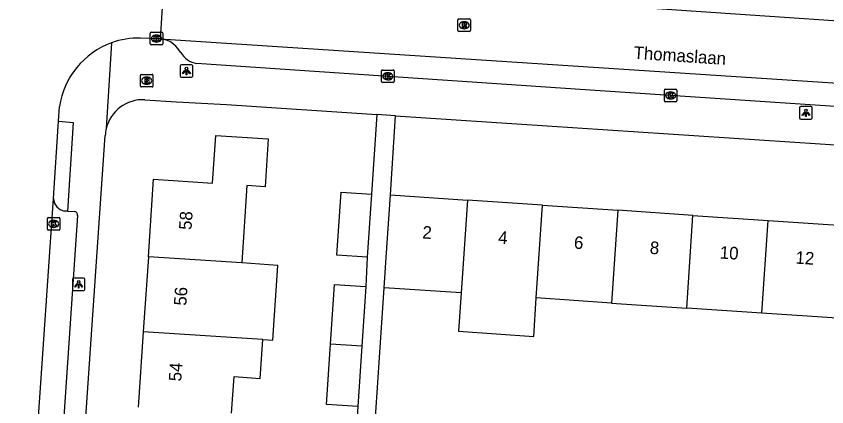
# Model space of a CAD drawing. Extents: x 161848 to 162726, y 385382 to 386521.
# Drawn here: x 162036.6 to 162101.1, y 385964.2 to 385995.3 of the extents above; entities that cross this region are included whole.
import ezdxf

# ---------------------------------------------------------------- set-up
doc = ezdxf.new("R2010")
doc.units = 0
for name, color, linetype in [('IMGEO_Brandkraan', 7, 'Continuous'), ('IMGEO_Kolk', 7, 'Continuous'), ('IMGEO_Lichtpunt', 7, 'Continuous'), ('IMGEO_Muur', 7, 'Continuous'), ('IMGEO_Openbare_ruimte_label', 7, 'Continuous'), ('IMGEO_Pand', 7, 'Continuous'), ('IMGEO_Pand_nummerreeks', 7, 'Continuous'), ('IMGEO_Rijbaan_lokaal_open', 7, 'Continuous'), ('IMGEO_Rioolput', 7, 'Continuous'), ('IMGEO_Voetpad_open', 7, 'Continuous')]:
    doc.layers.add(name, color=color, linetype=linetype)

msp = doc.modelspace()

# ---------------------------------------------------------------- linework, layer by layer
at = {"layer": 'IMGEO_Brandkraan'}
for p, q in [((162046.491, 385989.738), (162046.491, 385990.59)), ((162046.566, 385990.664), (162047.418, 385990.664)), ((162047.492, 385990.59), (162047.492, 385989.738)), ((162047.002, 385989.884), (162046.977, 385989.884)), ((162046.979, 385990.444), (162047.004, 385990.444)), ((162047.418, 385989.664), (162046.566, 385989.664))]:
    msp.add_line(p, q, dxfattribs=at)
for points in [[(162046.491, 385989.738), (162046.491, 385990.59)], [(162046.566, 385990.664), (162047.418, 385990.664)], [(162047.492, 385990.59), (162047.492, 385989.738)], [(162046.839, 385990.364), (162046.839, 385989.964), (162047.052, 385989.964)], [(162047.07, 385990.364), (162046.839, 385990.364)], [(162047.018, 385990.283), (162046.964, 385990.283), (162046.964, 385990.207)], [(162046.964, 385990.207), (162047.017, 385990.207)], [(162047.026, 385990.131), (162046.964, 385990.131), (162046.964, 385990.05)], [(162046.964, 385990.05), (162047.026, 385990.05)], [(162047.418, 385989.664), (162046.566, 385989.664)]]:
    msp.add_lwpolyline(points, dxfattribs=at)
for centre, radius, start, end in [((162046.568, 385990.588), 0.0765, 91.55205, 178.44795), ((162046.568, 385990.588), 0.0765, 91.55205, 178.44795), ((162047.416, 385990.588), 0.0765, 1.55205, 88.44795), ((162047.416, 385990.588), 0.0765, 1.55205, 88.44795), ((162047.019, 385990.245), 0.0379, 267.82845, 90.93552), ((162047.027, 385990.09), 0.0404, 269.87594, 90.50774), ((162047.058, 385990.215), 0.251, 268.66757, 293.53466), ((162047.074, 385990.219), 0.145, 59.4692, 91.53667), ((162047.099, 385990.266), 0.0922, 285.51372, 58.15012), ((162047.104, 385990.074), 0.105, 301.31148, 78.98903), ((162046.568, 385989.74), 0.0765, 181.55205, 268.44795), ((162046.568, 385989.74), 0.0765, 181.55205, 268.44795), ((162047.416, 385989.74), 0.0765, 271.55205, 358.44795), ((162047.416, 385989.74), 0.0765, 271.55205, 358.44795)]:
    msp.add_arc(centre, radius, start, end, dxfattribs=at)
for centre, major_axis, ratio, start_param, end_param in [((162046.978, 385990.164), (-0.387, 0.002), 0.722429, 4.712389, 7.853982), ((162047.003, 385990.164), (-0.39, 0.002), 0.717154, 1.570796, 4.712389)]:
    msp.add_ellipse(centre, major_axis=major_axis, ratio=ratio, start_param=start_param, end_param=end_param, dxfattribs=at)
at = {"layer": 'IMGEO_Kolk'}
for p, q in [((162047.27, 385993.092), (162047.27, 385993.944)), ((162047.345, 385994.018), (162048.197, 385994.018)), ((162047.758, 385993.798), (162047.783, 385993.798)), ((162048.271, 385993.944), (162048.271, 385993.092)), ((162047.781, 385993.238), (162047.756, 385993.238)), ((162048.197, 385993.018), (162047.345, 385993.018)), ((162065.683, 385990.087), (162065.683, 385990.939)), ((162065.758, 385991.013), (162066.61, 385991.013)), ((162066.171, 385990.793), (162066.196, 385990.793)), ((162066.684, 385990.939), (162066.684, 385990.087)), ((162066.61, 385990.013), (162065.758, 385990.013)), ((162066.194, 385990.233), (162066.169, 385990.233)), ((162088.2, 385988.562), (162088.2, 385989.414)), ((162088.275, 385989.488), (162089.127, 385989.488)), ((162088.688, 385989.268), (162088.713, 385989.268)), ((162089.201, 385989.414), (162089.201, 385988.562)), ((162088.711, 385988.708), (162088.686, 385988.708)), ((162089.127, 385988.488), (162088.275, 385988.488)), ((162039.087, 385978.327), (162039.087, 385979.179)), ((162039.162, 385979.253), (162040.014, 385979.253)), ((162039.575, 385979.033), (162039.6, 385979.033)), ((162040.088, 385979.179), (162040.088, 385978.327)), ((162040.014, 385978.253), (162039.162, 385978.253)), ((162039.598, 385978.473), (162039.573, 385978.473))]:
    msp.add_line(p, q, dxfattribs=at)
for points in [[(162047.27, 385993.092), (162047.27, 385993.944)], [(162047.345, 385994.018), (162048.197, 385994.018)], [(162047.591, 385993.718), (162047.714, 385993.718), (162047.714, 385993.567), (162047.844, 385993.718), (162048.008, 385993.718), (162047.862, 385993.567), (162048.015, 385993.318), (162047.863, 385993.318), (162047.778, 385993.482), (162047.714, 385993.415), (162047.714, 385993.318), (162047.591, 385993.318), (162047.591, 385993.718)], [(162048.271, 385993.944), (162048.271, 385993.092)], [(162048.197, 385993.018), (162047.345, 385993.018)], [(162065.683, 385990.087), (162065.683, 385990.939)], [(162065.758, 385991.013), (162066.61, 385991.013)], [(162066.004, 385990.713), (162066.127, 385990.713), (162066.127, 385990.562), (162066.257, 385990.713), (162066.421, 385990.713), (162066.275, 385990.562), (162066.428, 385990.313), (162066.276, 385990.313), (162066.191, 385990.477), (162066.127, 385990.41), (162066.127, 385990.313), (162066.004, 385990.313), (162066.004, 385990.713)], [(162066.684, 385990.939), (162066.684, 385990.087)], [(162066.61, 385990.013), (162065.758, 385990.013)], [(162088.2, 385988.562), (162088.2, 385989.414)], [(162088.275, 385989.488), (162089.127, 385989.488)], [(162089.201, 385989.414), (162089.201, 385988.562)], [(162088.521, 385989.188), (162088.644, 385989.188), (162088.644, 385989.037), (162088.774, 385989.188), (162088.938, 385989.188), (162088.792, 385989.037), (162088.945, 385988.788), (162088.793, 385988.788), (162088.708, 385988.952), (162088.644, 385988.885), (162088.644, 385988.788), (162088.521, 385988.788), (162088.521, 385989.188)], [(162089.127, 385988.488), (162088.275, 385988.488)], [(162039.087, 385978.327), (162039.087, 385979.179)], [(162039.162, 385979.253), (162040.014, 385979.253)], [(162039.408, 385978.953), (162039.531, 385978.953), (162039.531, 385978.802), (162039.661, 385978.953), (162039.825, 385978.953), (162039.679, 385978.802), (162039.832, 385978.553), (162039.68, 385978.553), (162039.595, 385978.717), (162039.531, 385978.65), (162039.531, 385978.553), (162039.408, 385978.553), (162039.408, 385978.953)], [(162040.088, 385979.179), (162040.088, 385978.327)], [(162040.014, 385978.253), (162039.162, 385978.253)]]:
    msp.add_lwpolyline(points, dxfattribs=at)
for centre, start, end in [((162047.347, 385993.942), 91.55205, 178.44795), ((162047.347, 385993.942), 91.55205, 178.44795), ((162048.195, 385993.942), 1.55205, 88.44795), ((162048.195, 385993.942), 1.55205, 88.44795), ((162047.347, 385993.094), 181.55205, 268.44795), ((162047.347, 385993.094), 181.55205, 268.44795), ((162048.195, 385993.094), 271.55205, 358.44795), ((162048.195, 385993.094), 271.55205, 358.44795), ((162065.76, 385990.937), 91.55205, 178.44795), ((162065.76, 385990.937), 91.55205, 178.44795), ((162066.608, 385990.937), 1.55205, 88.44795), ((162066.608, 385990.937), 1.55205, 88.44795), ((162065.76, 385990.089), 181.55205, 268.44795), ((162065.76, 385990.089), 181.55205, 268.44795), ((162066.608, 385990.089), 271.55205, 358.44795), ((162066.608, 385990.089), 271.55205, 358.44795), ((162088.277, 385989.412), 91.55205, 178.44795), ((162088.277, 385989.412), 91.55205, 178.44795), ((162089.125, 385989.412), 1.55205, 88.44795), ((162089.125, 385989.412), 1.55205, 88.44795), ((162088.277, 385988.564), 181.55205, 268.44795), ((162088.277, 385988.564), 181.55205, 268.44795), ((162089.125, 385988.564), 271.55205, 358.44795), ((162089.125, 385988.564), 271.55205, 358.44795), ((162039.164, 385979.177), 91.55205, 178.44795), ((162039.164, 385979.177), 91.55205, 178.44795), ((162040.012, 385979.177), 1.55205, 88.44795), ((162040.012, 385979.177), 1.55205, 88.44795), ((162039.164, 385978.329), 181.55205, 268.44795), ((162039.164, 385978.329), 181.55205, 268.44795), ((162040.012, 385978.329), 271.55205, 358.44795), ((162040.012, 385978.329), 271.55205, 358.44795)]:
    msp.add_arc(centre, 0.0765, start, end, dxfattribs=at)
for centre, major_axis, ratio, start_param, end_param in [((162047.757, 385993.518), (-0.387, 0.002), 0.722429, 4.712389, 7.853982), ((162047.782, 385993.518), (-0.39, 0.002), 0.717154, 1.570796, 4.712389), ((162066.17, 385990.513), (-0.387, 0.002), 0.722429, 4.712389, 7.853982), ((162066.195, 385990.513), (-0.39, 0.002), 0.717154, 1.570796, 4.712389), ((162088.687, 385988.988), (-0.387, 0.002), 0.722429, 4.712389, 7.853982), ((162088.712, 385988.988), (-0.39, 0.002), 0.717154, 1.570796, 4.712389), ((162039.574, 385978.753), (-0.387, 0.002), 0.722429, 4.712389, 7.853982), ((162039.599, 385978.753), (-0.39, 0.002), 0.717154, 1.570796, 4.712389)]:
    msp.add_ellipse(centre, major_axis=major_axis, ratio=ratio, start_param=start_param, end_param=end_param, dxfattribs=at)
at = {"layer": 'IMGEO_Lichtpunt'}
for p, q in [((162049.657, 385991.334), (162049.657, 385990.527)), ((162049.657, 385991.334), (162049.657, 385990.527)), ((162050.559, 385991.429), (162049.751, 385991.429)), ((162050.559, 385991.429), (162049.751, 385991.429)), ((162050.653, 385990.527), (162050.653, 385991.334)), ((162050.653, 385990.527), (162050.653, 385991.334)), ((162049.751, 385990.433), (162050.559, 385990.433)), ((162049.751, 385990.433), (162050.559, 385990.433)), ((162098.97, 385988.004), (162098.97, 385987.197)), ((162098.97, 385988.004), (162098.97, 385987.197)), ((162099.872, 385988.099), (162099.064, 385988.099)), ((162099.872, 385988.099), (162099.064, 385988.099)), ((162099.966, 385987.197), (162099.966, 385988.004)), ((162099.966, 385987.197), (162099.966, 385988.004)), ((162099.064, 385987.103), (162099.872, 385987.103)), ((162099.064, 385987.103), (162099.872, 385987.103)), ((162041.981, 385974.44), (162041.173, 385974.44)), ((162041.981, 385974.44), (162041.173, 385974.44)), ((162041.079, 385974.345), (162041.079, 385973.538)), ((162041.079, 385974.345), (162041.079, 385973.538)), ((162042.075, 385973.538), (162042.075, 385974.345)), ((162042.075, 385973.538), (162042.075, 385974.345)), ((162041.173, 385973.444), (162041.981, 385973.444)), ((162041.173, 385973.444), (162041.981, 385973.444))]:
    msp.add_line(p, q, dxfattribs=at)
for points in [[(162050.031, 385990.998), (162050.07, 385990.97), (162049.882, 385990.708), (162049.844, 385990.735), (162050.031, 385990.998)], [(162050.133, 385990.95), (162050.18, 385990.95), (162050.18, 385990.628), (162050.133, 385990.628), (162050.133, 385990.95)], [(162050.243, 385990.97), (162050.281, 385990.997), (162050.468, 385990.735), (162050.429, 385990.707), (162050.243, 385990.97)], [(162099.344, 385987.668), (162099.383, 385987.64), (162099.195, 385987.378), (162099.157, 385987.405), (162099.344, 385987.668)], [(162099.446, 385987.62), (162099.493, 385987.62), (162099.493, 385987.298), (162099.446, 385987.298), (162099.446, 385987.62)], [(162099.556, 385987.64), (162099.594, 385987.667), (162099.781, 385987.405), (162099.742, 385987.377), (162099.556, 385987.64)], [(162041.453, 385974.009), (162041.492, 385973.981), (162041.304, 385973.719), (162041.266, 385973.746), (162041.453, 385974.009)], [(162041.555, 385973.961), (162041.602, 385973.961), (162041.602, 385973.639), (162041.555, 385973.639), (162041.555, 385973.961)], [(162041.665, 385973.981), (162041.703, 385974.008), (162041.89, 385973.746), (162041.851, 385973.718), (162041.665, 385973.981)]]:
    msp.add_lwpolyline(points, dxfattribs=at)
for centre in [(162050.156, 385991.132), (162099.469, 385987.802), (162041.578, 385974.143)]:
    msp.add_circle(centre, 0.0994, dxfattribs=at)
for centre, start, end in [((162049.751, 385991.334), 90, 180), ((162049.751, 385991.334), 90, 180), ((162050.559, 385991.334), 0, 90), ((162050.559, 385991.334), 0, 90), ((162049.751, 385990.527), 180, 270), ((162049.751, 385990.527), 180, 270), ((162050.559, 385990.527), 270, 0), ((162050.559, 385990.527), 270, 360), ((162099.064, 385988.004), 90, 180), ((162099.064, 385988.004), 90, 180), ((162099.872, 385988.004), 0, 90), ((162099.872, 385988.004), 0, 90), ((162099.064, 385987.197), 180, 270), ((162099.064, 385987.197), 180, 270), ((162099.872, 385987.197), 270, 0), ((162099.872, 385987.197), 270, 360), ((162041.173, 385974.345), 90, 180), ((162041.173, 385974.345), 90, 180), ((162041.981, 385974.345), 0, 90), ((162041.981, 385974.345), 0, 90), ((162041.173, 385973.538), 180, 270), ((162041.173, 385973.538), 180, 270), ((162041.981, 385973.538), 270, 0), ((162041.981, 385973.538), 270, 360)]:
    msp.add_arc(centre, 0.0946, start, end, dxfattribs=at)
at = {"layer": 'IMGEO_Muur'}
msp.add_lwpolyline([(162053.355, 385988.257), (162065.312, 385987.466)], dxfattribs=at)
at = {"layer": 'IMGEO_Pand'}
for points in [[(162047.125, 385976.142), (162047.541, 385982.308), (162052.231, 385981.992), (162052.488, 385985.804), (162056.669, 385985.523), (162056.412, 385981.711), (162054.971, 385981.807), (162054.555, 385975.643)], [(162064.553, 385976.102), (162062.135, 385976.263), (162062.47, 385981.281), (162064.888, 385981.12)], [(162064.888, 385981.12), (162064.553, 385976.102)], [(162065.894, 385973.665), (162066.056, 385976.07), (162066.392, 385981.058)], [(162066.392, 385981.058), (162072.527, 385980.644)], [(162072.527, 385980.644), (162072.024, 385973.255)], [(162078.51, 385980.24), (162072.527, 385980.644)], [(162078.008, 385972.855), (162078.51, 385980.24)], [(162078.51, 385980.24), (162084.493, 385979.837)], [(162084.493, 385979.837), (162084.001, 385972.454)], [(162090.475, 385979.433), (162084.493, 385979.837)], [(162089.981, 385972.055), (162090.475, 385979.433)], [(162090.475, 385979.433), (162096.458, 385979.029)], [(162095.965, 385971.655), (162096.458, 385979.029)], [(162096.458, 385979.029), (162102.441, 385978.625)], [(162047.125, 385976.142), (162046.721, 385970.155)], [(162054.555, 385975.643), (162047.125, 385976.142)], [(162056.236, 385969.535), (162057.027, 385969.484), (162057.43, 385975.45), (162054.555, 385975.643)], [(162061.618, 385969.185), (162061.935, 385973.941), (162064.448, 385973.773)], [(162064.448, 385973.773), (162064.132, 385969.021)], [(162072.024, 385973.255), (162065.894, 385973.665)], [(162072.024, 385973.255), (162071.816, 385970.201), (162077.801, 385969.793), (162078.008, 385972.855)], [(162084.001, 385972.454), (162078.008, 385972.855)], [(162084.001, 385972.454), (162089.981, 385972.055)], [(162095.965, 385971.655), (162089.981, 385972.055)], [(162101.953, 385971.254), (162095.965, 385971.655)], [(162046.721, 385970.155), (162046.317, 385964.168)], [(162056.236, 385969.535), (162054.152, 385969.671), (162046.721, 385970.155)], [(162053.748, 385963.681), (162053.944, 385966.589), (162056.027, 385966.449), (162056.236, 385969.535)], [(162063.811, 385964.208), (162061.298, 385964.376), (162061.618, 385969.185)], [(162064.132, 385969.021), (162061.618, 385969.185)], [(162064.132, 385969.021), (162063.811, 385964.208)]]:
    msp.add_lwpolyline(points, dxfattribs=at)
at = {"layer": 'IMGEO_Rijbaan_lokaal_open'}
for points in [[(162048.377, 385998.497), (162048.056, 385993.508)], [(162072.445, 385996.95), (162078.632, 385996.529), (162120.807, 385993.662), (162130.556, 385992.978), (162144.838, 385991.962)], [(162048.056, 385993.508), (162046.488, 385993.561)], [(162048.056, 385993.508), (162134.499, 385987.854)], [(162039.981, 385986.928), (162040.057, 385988.095)], [(162039.579, 385980.773), (162039.981, 385986.928)], [(162036.606, 385937.482), (162039.579, 385980.773)]]:
    msp.add_lwpolyline(points, dxfattribs=at)
for centre, radius, start, end in [((162046.372, 385987.181), 6.381, 109.86355, 171.76156), ((162046.373, 385987.18), 6.382, 88.9704, 109.87288)]:
    msp.add_arc(centre, radius, start, end, dxfattribs=at)
at = {"layer": 'IMGEO_Rioolput'}
for p, q in [((162071.771, 385994.152), (162071.771, 385995.004)), ((162071.846, 385995.078), (162072.698, 385995.078)), ((162072.772, 385995.004), (162072.772, 385994.152)), ((162072.259, 385994.858), (162072.284, 385994.858)), ((162072.698, 385994.078), (162071.846, 385994.078)), ((162072.282, 385994.298), (162072.257, 385994.298))]:
    msp.add_line(p, q, dxfattribs=at)
for points in [[(162071.771, 385994.152), (162071.771, 385995.004)], [(162071.846, 385995.078), (162072.698, 385995.078)], [(162072.772, 385995.004), (162072.772, 385994.152)], [(162072.36, 385994.776), (162072.108, 385994.778), (162072.108, 385994.378)], [(162072.108, 385994.378), (162072.232, 385994.378), (162072.232, 385994.54), (162072.243, 385994.54)], [(162072.286, 385994.697), (162072.232, 385994.697), (162072.232, 385994.616)], [(162072.232, 385994.616), (162072.284, 385994.616)], [(162072.29, 385994.511), (162072.361, 385994.378), (162072.501, 385994.378), (162072.436, 385994.504)], [(162072.698, 385994.078), (162071.846, 385994.078)]]:
    msp.add_lwpolyline(points, dxfattribs=at)
for centre, radius, start, end in [((162071.848, 385995.002), 0.0765, 91.55205, 178.44795), ((162071.848, 385995.002), 0.0765, 91.55205, 178.44795), ((162072.696, 385995.002), 0.0765, 1.55205, 88.44795), ((162072.696, 385995.002), 0.0765, 1.55205, 88.44795), ((162072.242, 385994.487), 0.0533, 26.02933, 88.69889), ((162072.268, 385994.805), 0.19, 274.7715, 282.96867), ((162072.292, 385994.601), 0.0964, 77.00612, 93.18647), ((162072.306, 385994.658), 0.0378, 276.66336, 79.67722), ((162072.359, 385994.666), 0.109, 350.36119, 89.41601), ((162072.357, 385994.666), 0.112, 277.58423, 350.98172), ((162072.341, 385994.451), 0.108, 29.51342, 73.79051), ((162071.848, 385994.154), 0.0765, 181.55205, 268.44795), ((162071.848, 385994.154), 0.0765, 181.55205, 268.44795), ((162072.696, 385994.154), 0.0765, 271.55205, 358.44795), ((162072.696, 385994.154), 0.0765, 271.55205, 358.44795)]:
    msp.add_arc(centre, radius, start, end, dxfattribs=at)
for centre, major_axis, ratio, start_param, end_param in [((162072.258, 385994.578), (-0.387, 0.002), 0.722429, 4.712389, 7.853982), ((162072.283, 385994.578), (-0.39, 0.002), 0.717154, 1.570796, 4.712389)]:
    msp.add_ellipse(centre, major_axis=major_axis, ratio=ratio, start_param=start_param, end_param=end_param, dxfattribs=at)
at = {"layer": 'IMGEO_Voetpad_open'}
for points in [[(162044.204, 385993.182), (162043.773, 385986.348)], [(162049.717, 385992.417), (162049.44, 385992.761)], [(162122.5, 385986.713), (162120.725, 385986.832), (162115.736, 385987.167), (162081.9, 385989.441), (162050.953, 385991.529)], [(162046.839, 385988.641), (162049.375, 385988.473), (162053.355, 385988.257), (162065.312, 385987.466)], [(162065.312, 385987.466), (162064.888, 385981.12)], [(162066.809, 385987.367), (162065.312, 385987.466)], [(162066.392, 385981.058), (162066.809, 385987.367)], [(162066.809, 385987.367), (162115.08, 385984.174)], [(162039.981, 385986.928), (162041.141, 385986.829), (162040.697, 385979.764)], [(162040.143, 385933.992), (162043.697, 385985.789)], [(162040.697, 385979.764), (162040.456, 385979.777)], [(162040.697, 385979.764), (162041.251, 385979.733)], [(162041.478, 385979.423), (162038.701, 385938.4)], [(162064.553, 385976.102), (162064.448, 385973.773)], [(162066.294, 385961.702), (162065.112, 385961.78), (162065.894, 385973.665)], [(162063.811, 385964.208), (162063.64, 385961.799)]]:
    msp.add_lwpolyline(points, dxfattribs=at)
for centre, radius, start, end in [((162047.853, 385991.476), 2.042, 38.99033, 84.29465), ((162051.258, 385993.258), 1.756, 208.62522, 259.98432), ((162046.669, 385985.673), 2.973, 86.71414, 166.87002), ((162046.741, 385985.66), 3.047, 166.9463, 177.56911), ((162040.633, 385980.817), 1.055, 182.37597, 260.3533), ((162041.246, 385979.491), 0.242, 343.68164, 88.74586)]:
    msp.add_arc(centre, radius, start, end, dxfattribs=at)

# ---------------------------------------------------------------- texts
at = {"layer": 'IMGEO_Openbare_ruimte_label'}
msp.add_text('Thomaslaan', height=1, rotation=356.15925, dxfattribs=at).set_placement((162085.732, 385991.912))
at = {"layer": 'IMGEO_Pand_nummerreeks'}
for s, rotation, p in [('58', 86.13907, (162050.555, 385978.251)), ('2', 356.13952, (162068.911, 385977.601)), ('4', 356.13952, (162074.947, 385977.194)), ('6', 356.13952, (162080.98, 385976.787)), ('8', 356.13952, (162087.017, 385976.379)), ('10', 356.13952, (162092.59, 385976.003)), ('12', 356.13952, (162098.618, 385975.596)), ('56', 86.13847, (162050.148, 385972.22)), ('54', 86.13847, (162049.741, 385966.191))]:
    msp.add_text(s, height=1, rotation=rotation, dxfattribs=at).set_placement(p)

doc.saveas('drawing.dxf')
